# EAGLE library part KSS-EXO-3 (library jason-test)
CMOS programmable frequency divider Frequencies available (MHz): 12.00 12.288 12.80 14.31818 14.7456 16.00 17.734476 18.432 19.6608 20.00
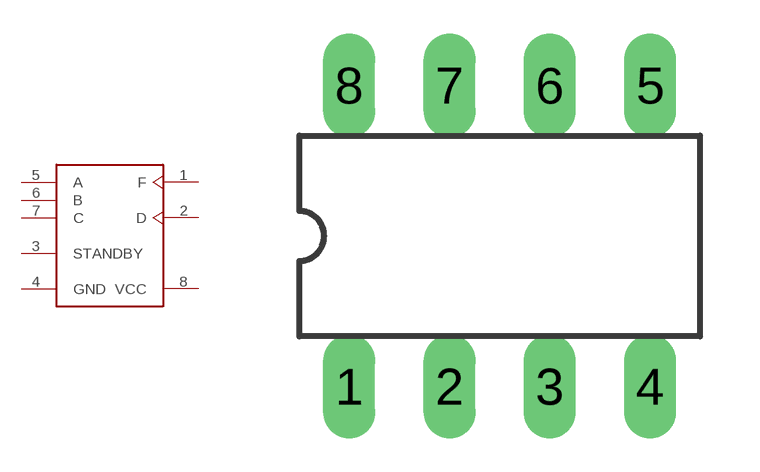
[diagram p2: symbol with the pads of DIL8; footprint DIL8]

Designator prefix -

## KSS-EXO-3  [DIL8]
1  F  out
2  D  out
3  STANDBY  in
4  GND  pwr
5  A  in
6  B  in
7  C  in
8  VCC  pwr

## Footprint DIL8 (pad centres in mm)
Dual In Line package type P
drill 0.813 long: 1 -3.81,-3.81; 2 -1.27,-3.81; 3 1.27,-3.81; 4 3.81,-3.81; 5 3.81,3.81; 6 1.27,3.81; 7 -1.27,3.81; 8 -3.81,3.81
